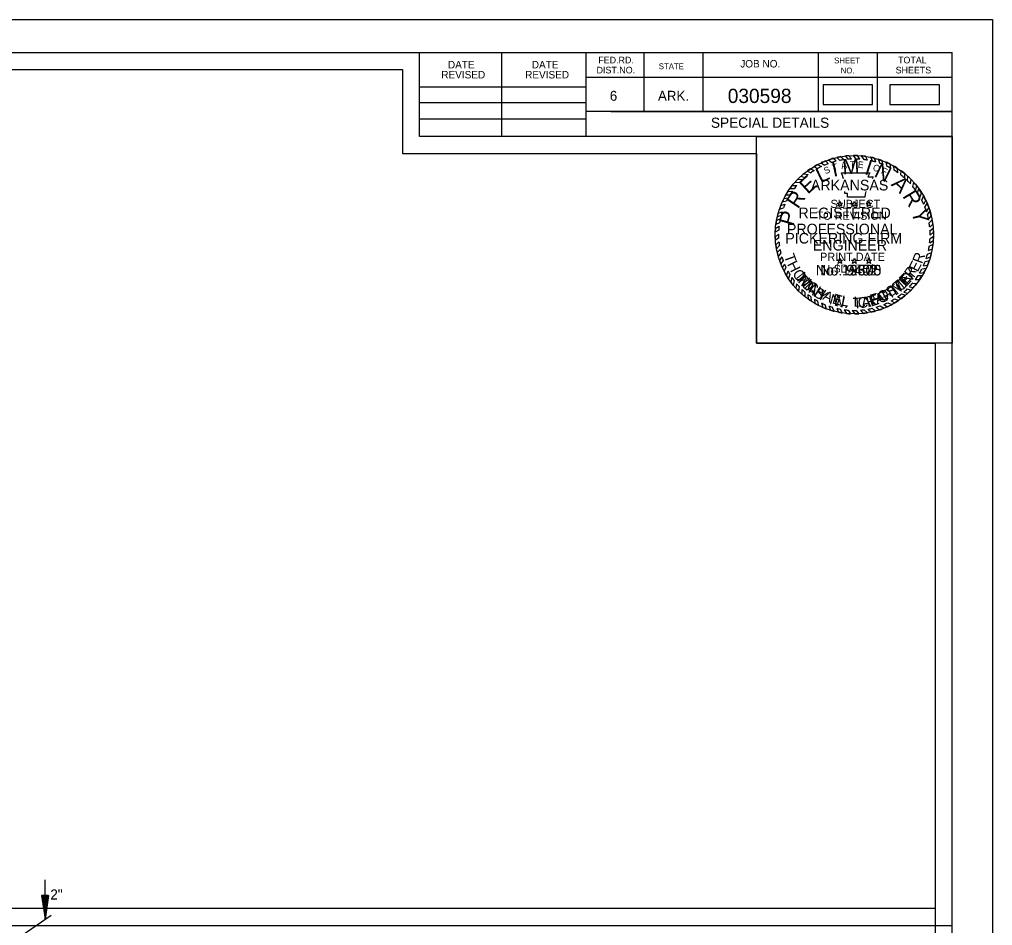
# Model space of a CAD drawing. Extents: x 1369904 to 1370238, y 380119 to 380332.
# Drawn here: x 1370123.3 to 1370237.7, y 380225.5 to 380332.1 of the extents above; entities that cross this region are included whole.
import ezdxf

# ---------------------------------------------------------------- set-up
doc = ezdxf.new("R2010")
doc.units = 0
for name, color, linetype in [('Default', 7, 'Continuous'), ('R_Border', 7, 'Continuous'), ('R_Border Notes', 7, 'Continuous'), ('R_Border Plan-Plan', 7, 'Continuous'), ('R_No Plot', 7, 'Continuous'), ('STAMP_PE_CRAFTON', 7, 'Continuous'), ('STAMP_PE_FOSTER', 7, 'Continuous'), ('STAMP_PE_SEAL-INFO', 7, 'Continuous'), ('STAMP_PE_TAEGTMEYER', 7, 'Continuous'), ('STAMP_PE_TXT', 7, 'Continuous'), ('STAMP_PRELIMINARY', 7, 'Continuous')]:
    doc.layers.add(name, color=color, linetype=linetype)

msp = doc.modelspace()

# ---------------------------------------------------------------- linework, layer by layer
at = {"layer": 'Default'}
for p, q in [((1370126.28, 380226.23), (1370126.28, 380230.86)), ((1370125.86, 380229.02), (1370126.28, 380226.23)), ((1370126.7, 380229.02), (1370125.86, 380229.02)), ((1370125.93, 380229.02), (1370126.28, 380226.69)), ((1370126.01, 380229.02), (1370126.28, 380227.17)), ((1370126.08, 380229.02), (1370126.28, 380227.64)), ((1370126.15, 380229.02), (1370126.28, 380228.11)), ((1370126.22, 380229.02), (1370126.28, 380228.57)), ((1370126.7, 380229.02), (1370126.28, 380226.23)), ((1370126.41, 380229.02), (1370126.28, 380228.11)), ((1370126.56, 380229.02), (1370126.28, 380227.17)), ((1370126.63, 380229.02), (1370126.28, 380226.69)), ((1370126.49, 380229.02), (1370126.28, 380227.64)), ((1370126.35, 380229.02), (1370126.28, 380228.57)), ((1370123.57, 380224.35), (1370126.98, 380226.71))]:
    msp.add_line(p, q, dxfattribs=at)
for points in [[(1370217.79, 380322.14), (1370223.62, 380322.14), (1370223.62, 380324.45), (1370217.79, 380324.45)], [(1370225.66, 380322.14), (1370231.49, 380322.14), (1370231.49, 380324.45), (1370225.66, 380324.45)]]:
    msp.add_lwpolyline(points, close=True, dxfattribs=at)
at = {"layer": 'R_Border'}
for p, q in [((1369916.79, 380328.24), (1370232.97, 380328.24)), ((1370170.33, 380318.36), (1370170.33, 380328.24)), ((1370180.01, 380318.36), (1370180.01, 380328.24)), ((1370189.87, 380328.24), (1370189.87, 380318.36)), ((1370196.71, 380328.24), (1370196.71, 380321.3)), ((1370203.65, 380328.24), (1370203.65, 380321.3)), ((1370217.23, 380328.24), (1370217.23, 380321.3)), ((1370224.17, 380328.24), (1370224.17, 380321.3)), ((1370232.97, 380122.78), (1370232.97, 380328.24)), ((1370232.97, 380325.3), (1370189.87, 380325.3)), ((1370232.97, 380325.32), (1370232.97, 380325.32)), ((1370170.33, 380324.22), (1370189.87, 380324.22)), ((1370170.33, 380322.36), (1370189.87, 380322.36)), ((1370232.97, 380321.3), (1370189.87, 380321.3)), ((1370192.83, 380321.3), (1370232.97, 380321.3)), ((1370170.33, 380320.42), (1370189.87, 380320.42)), ((1370232.97, 380318.36), (1370170.33, 380318.36))]:
    msp.add_line(p, q, dxfattribs=at)
at = {"layer": 'R_Border Plan-Plan'}
msp.add_line((1369916.79, 380225.51), (1370232.97, 380225.51), dxfattribs=at)
at = {"layer": 'R_No Plot'}
for points in [[(1369904.38, 380332.13), (1370237.72, 380332.13), (1370237.72, 380118.79), (1369904.38, 380118.79)], [(1370230.97, 380227.51), (1369918.79, 380227.51), (1369918.79, 380326.24), (1370168.33, 380326.24), (1370168.33, 380316.36), (1370185.87, 380316.36), (1370209.97, 380316.36), (1370209.97, 380294.02), (1370230.97, 380294.02)], [(1369918.79, 380326.24), (1370168.33, 380326.24), (1370168.33, 380316.36), (1370185.87, 380316.36), (1370209.97, 380316.36), (1370209.97, 380294.02), (1370230.97, 380294.02), (1370230.97, 380124.78), (1369918.79, 380124.78)], [(1370209.97, 380318.36), (1370232.97, 380318.36), (1370232.97, 380294.02), (1370209.97, 380294.02)]]:
    msp.add_lwpolyline(points, close=True, dxfattribs=at)
at = {"layer": 'STAMP_PE_SEAL-INFO'}
for p, q in [((1370217.58, 380315.27), (1370217.97, 380314.99)), ((1370218.08, 380315.49), (1370218.38, 380315.16)), ((1370218.43, 380315.61), (1370218.81, 380315.31)), ((1370219.02, 380315.8), (1370219.31, 380315.45)), ((1370219.41, 380315.89), (1370219.77, 380315.55)), ((1370219.89, 380315.99), (1370220.19, 380315.62)), ((1370220.41, 380316.06), (1370220.69, 380315.68)), ((1370221.14, 380315.71), (1370220.83, 380316.1)), ((1370221.64, 380315.71), (1370221.36, 380316.12)), ((1370222.1, 380315.69), (1370221.84, 380316.12)), ((1370222.61, 380315.64), (1370222.31, 380316.08)), ((1370223.03, 380315.58), (1370222.77, 380316.03)), ((1370223.59, 380315.46), (1370223.42, 380315.92)), ((1370223.99, 380315.35), (1370223.84, 380315.82)), ((1370224.45, 380315.2), (1370224.31, 380315.68)), ((1370224.86, 380315.04), (1370224.72, 380315.54)), ((1370225.33, 380314.84), (1370225.22, 380315.33)), ((1370215.89, 380314.3), (1370216.35, 380314.09)), ((1370216.31, 380314.56), (1370216.75, 380314.36)), ((1370216.7, 380314.81), (1370217.13, 380314.58)), ((1370217.14, 380315.06), (1370217.61, 380314.83)), ((1370219.94, 380314.09), (1370223.29, 380314.09)), ((1370220.07, 380313.78), (1370219.94, 380314.09)), ((1370223.29, 380314.09), (1370223.06, 380313.6)), ((1370225.77, 380314.61), (1370225.68, 380315.12)), ((1370226.16, 380314.38), (1370226.12, 380314.88)), ((1370226.59, 380314.09), (1370226.56, 380314.61)), ((1370226.95, 380313.83), (1370226.99, 380314.31)), ((1370214.51, 380313), (1370215.03, 380312.96)), ((1370214.83, 380313.35), (1370215.38, 380313.3)), ((1370215.17, 380313.67), (1370215.63, 380313.53)), ((1370215.51, 380313.97), (1370216.04, 380313.87)), ((1370220.17, 380313.49), (1370220.07, 380313.78)), ((1370220.18, 380313.37), (1370220.17, 380313.49)), ((1370223.06, 380313.6), (1370223.7, 380313.6)), ((1370223.7, 380313.6), (1370223.55, 380313.37)), ((1370227.4, 380313.46), (1370227.42, 380313.98)), ((1370227.71, 380313.16), (1370227.78, 380313.66)), ((1370228.07, 380312.79), (1370228.14, 380313.32)), ((1370228.35, 380312.47), (1370228.48, 380312.94)), ((1370213.65, 380311.88), (1370214.17, 380311.91)), ((1370213.89, 380312.22), (1370214.39, 380312.22)), ((1370214.17, 380312.59), (1370214.71, 380312.61)), ((1370220.37, 380311.66), (1370220.34, 380311.88)), ((1370222.81, 380311.88), (1370222.73, 380311.57)), ((1370228.67, 380312.06), (1370228.81, 380312.56)), ((1370228.89, 380311.74), (1370229.07, 380312.2)), ((1370212.99, 380310.66), (1370213.49, 380310.77)), ((1370213.18, 380311.05), (1370213.67, 380311.12)), ((1370213.41, 380311.48), (1370213.9, 380311.5)), ((1370220.68, 380311.66), (1370220.37, 380311.66)), ((1370220.68, 380311.23), (1370220.68, 380311.66)), ((1370222.71, 380311.23), (1370220.68, 380311.23)), ((1370222.73, 380311.57), (1370222.71, 380311.23)), ((1370229.2, 380311.24), (1370229.38, 380311.73)), ((1370229.4, 380310.88), (1370229.62, 380311.32)), ((1370229.63, 380310.39), (1370229.86, 380310.88)), ((1370212.5, 380309.32), (1370212.97, 380309.49)), ((1370212.65, 380309.82), (1370213.14, 380309.96)), ((1370212.8, 380310.23), (1370213.31, 380310.38)), ((1370229.77, 380310.06), (1370230.03, 380310.49)), ((1370229.96, 380309.51), (1370230.23, 380309.98)), ((1370230.07, 380309.14), (1370230.37, 380309.59)), ((1370212.76, 380308.67), (1370212.29, 380308.42)), ((1370212.39, 380308.91), (1370212.86, 380309.11)), ((1370230.21, 380308.58), (1370230.52, 380309.03)), ((1370230.27, 380308.2), (1370230.63, 380308.56)), ((1370212.58, 380307.35), (1370212.15, 380307.09)), ((1370212.61, 380307.77), (1370212.17, 380307.49)), ((1370212.67, 380308.21), (1370212.22, 380307.99)), ((1370230.34, 380307.69), (1370230.71, 380308.03)), ((1370230.37, 380307.28), (1370230.76, 380307.57)), ((1370212.56, 380306.86), (1370212.15, 380306.52)), ((1370212.57, 380306.45), (1370212.17, 380306.12)), ((1370230.33, 380305.85), (1370230.77, 380306.1)), ((1370230.37, 380306.35), (1370230.79, 380306.63)), ((1370230.39, 380306.76), (1370230.79, 380307.08)), ((1370212.6, 380305.95), (1370212.23, 380305.6)), ((1370212.65, 380305.52), (1370212.3, 380305.15)), ((1370212.73, 380305.06), (1370212.39, 380304.7)), ((1370230.19, 380304.96), (1370230.65, 380305.15)), ((1370230.28, 380305.46), (1370230.73, 380305.68)), ((1370212.82, 380304.65), (1370212.51, 380304.23)), ((1370212.95, 380304.2), (1370212.65, 380303.78)), ((1370213.09, 380303.78), (1370212.81, 380303.36)), ((1370229.8, 380303.63), (1370230.29, 380303.76)), ((1370229.94, 380304.01), (1370230.43, 380304.21)), ((1370230.09, 380304.51), (1370230.56, 380304.71)), ((1370213.25, 380303.35), (1370212.99, 380302.93)), ((1370213.43, 380302.97), (1370213.2, 380302.5)), ((1370229.43, 380302.78), (1370229.92, 380302.85)), ((1370229.59, 380303.12), (1370230.08, 380303.21)), ((1370213.66, 380302.51), (1370213.47, 380302.02)), ((1370213.9, 380302.1), (1370213.71, 380301.63)), ((1370214.1, 380301.79), (1370213.99, 380301.24)), ((1370228.64, 380301.51), (1370229.15, 380301.51)), ((1370228.98, 380302), (1370229.46, 380302)), ((1370229.16, 380302.28), (1370229.66, 380302.34)), ((1370214.38, 380301.4), (1370214.28, 380300.87)), ((1370214.68, 380301.02), (1370214.6, 380300.5)), ((1370214.99, 380300.69), (1370214.92, 380300.16)), ((1370215.31, 380300.36), (1370215.28, 380299.83)), ((1370227.7, 380300.42), (1370228.14, 380300.28)), ((1370227.95, 380300.68), (1370228.43, 380300.6)), ((1370228.34, 380301.11), (1370228.8, 380301.04)), ((1370215.65, 380300.05), (1370215.65, 380299.52)), ((1370216.01, 380299.75), (1370216.03, 380299.23)), ((1370216.35, 380299.5), (1370216.39, 380298.99)), ((1370216.78, 380299.22), (1370216.84, 380298.71)), ((1370226.22, 380299.26), (1370226.67, 380299.06)), ((1370226.56, 380299.48), (1370227, 380299.29)), ((1370227.02, 380299.83), (1370227.49, 380299.68)), ((1370227.29, 380300.05), (1370227.76, 380299.92)), ((1370217.13, 380299.02), (1370217.22, 380298.5)), ((1370217.61, 380298.77), (1370217.77, 380298.25)), ((1370217.98, 380298.6), (1370218.15, 380298.09)), ((1370218.47, 380298.41), (1370218.68, 380297.9)), ((1370218.88, 380298.27), (1370219.11, 380297.78)), ((1370219.39, 380298.13), (1370219.6, 380297.67)), ((1370219.79, 380298.05), (1370220.04, 380297.59)), ((1370223.56, 380298.14), (1370223.94, 380297.81)), ((1370224.02, 380298.26), (1370224.44, 380297.96)), ((1370224.52, 380298.42), (1370224.96, 380298.15)), ((1370224.94, 380298.59), (1370225.36, 380298.33)), ((1370225.4, 380298.8), (1370225.88, 380298.59)), ((1370225.8, 380299.01), (1370226.22, 380298.78)), ((1370220.29, 380297.97), (1370220.53, 380297.52)), ((1370220.73, 380297.92), (1370221, 380297.49)), ((1370221.21, 380297.89), (1370221.51, 380297.48)), ((1370221.67, 380297.89), (1370222.01, 380297.49)), ((1370222.19, 380297.92), (1370222.51, 380297.54)), ((1370222.63, 380297.96), (1370223, 380297.6)), ((1370223.07, 380298.03), (1370223.46, 380297.69))]:
    msp.add_line(p, q, dxfattribs=at)
for radius, start, end in [(9.32, 111.3124, 114.7026), (9.32, 105.2339, 109.0352), (8.91, 104.0352, 107.3615), (9.32, 99.7525, 102.7765), (8.91, 98.258, 101.0329), (9.32, 93.9381, 96.5517), (8.91, 92.1102, 95.0367), (9.32, 87.7298, 90.6707), (8.91, 85.9628, 88.9097), (9.32, 81.9732, 84.8236), (8.91, 79.9264, 82.696), (9.32, 75.3125, 77.9426), (8.91, 73.5575, 76.2314), (9.32, 69.6061, 72.3058), (8.91, 67.6248, 70.504), (9.32, 63.1329, 66.2704), (9.32, 123.6199, 126.5906), (8.91, 121.9746, 125.11), (9.32, 117.6544, 120.8099), (8.91, 115.6869, 119.1583), (8.91, 110.3086, 113.1659), (8.91, 61.1558, 64.3784), (9.32, 56.9003, 60.0942), (8.91, 54.9238, 58.2702), (9.32, 50.3492, 53.7159), (9.32, 135.4021, 138.3031), (8.91, 133.1331, 136.2562), (9.32, 129.7326, 132.5376), (8.91, 127.5297, 130.9683), (8.91, 48.3016, 52.0395), (8.91, 42.2212, 45.5512), (9.32, 44.3405, 47.3929), (9.32, 38.1247, 41.2316), (9.32, 147.0072, 149.899), (9.32, 141.6056, 144.4486), (8.91, 145.0197, 148.2104), (8.91, 139.301, 142.5873), (8.91, 36.135, 39.5311), (9.32, 31.9614, 35.4294), (9.32, 152.864, 155.5189), (8.91, 151.0315, 153.573), (8.91, 29.9032, 33.6645), (8.91, 23.7732, 27.2211), (9.32, 25.9391, 29.0125), (9.32, 158.4077, 161.0701), (8.91, 162.4331, 165.0013), (8.91, 156.3402, 159.2319), (8.91, 17.6802, 21.4251), (9.32, 19.9538, 23.3141), (9.32, 13.8421, 17.4447), (9.32, 170.0003, 172.6878), (9.32, 164.3068, 166.894), (8.91, 167.9048, 170.9039), (8.91, 11.5444, 15.2364), (9.32, 7.5852, 10.8621), (9.32, 175.7409, 178.2066), (8.91, 173.73, 176.4734), (8.91, 5.7599, 9.0606), (8.91, 359.7329, 3.0639), (9.32, 1.7215, 4.7268), (9.32, 181.7251, 184.1626), (8.91, 179.6454, 182.2633), (8.91, 353.8632, 357.1274), (9.32, 355.7156, 358.9569), (9.32, 187.4204, 190.1927), (8.91, 185.4539, 188.234), (8.91, 191.2274, 193.9858), (8.91, 348.0778, 351.3435), (9.32, 349.8305, 353.0885), (9.32, 193.0369, 195.9973), (9.32, 198.8967, 201.6281), (8.91, 196.9675, 199.8353), (8.91, 341.777, 345.0925), (9.32, 337.3837, 340.9933), (9.32, 343.8925, 347.035), (9.32, 204.5479, 207.4328), (8.91, 202.7761, 205.4791), (8.91, 329.5549, 333.2076), (8.91, 335.6038, 339.1858), (9.32, 331.4037, 334.9332), (9.32, 210.8636, 213.6571), (8.91, 208.7883, 211.7934), (8.91, 214.1838, 217.2747), (8.91, 323.5851, 327.4407), (9.32, 325.4405, 328.9872), (9.32, 216.6115, 219.491), (9.32, 222.48, 225.3801), (8.91, 220.3909, 223.3056), (8.91, 226.2494, 229.2407), (8.91, 310.7744, 314.3161), (8.91, 316.6531, 320.3711), (9.32, 318.2846, 321.8043), (9.32, 228.3665, 231.348), (8.91, 232.229, 234.9336), (9.32, 234.295, 236.9452), (8.91, 238.2223, 240.8353), (8.91, 299.0768, 302.1724), (8.91, 304.823, 308.5143), (9.32, 306.3721, 310.208), (9.32, 312.4518, 315.6633), (9.32, 240.1977, 242.8613), (8.91, 244.3204, 246.9486), (9.32, 246.576, 249.1558), (8.91, 250.3491, 253.1216), (8.91, 256.505, 259.1192), (8.91, 280.3459, 283.5814), (8.91, 286.6423, 289.9783), (9.32, 288.5709, 291.9733), (8.91, 292.8745, 296.1185), (9.32, 294.6481, 298.2166), (9.32, 300.621, 303.8703), (9.32, 252.5967, 255.3252), (9.32, 258.4433, 261.1398), (8.91, 262.3783, 265.2012), (9.32, 264.1978, 267.1009), (8.91, 268.3215, 271.277), (9.32, 270.2548, 273.3361), (8.91, 274.6157, 277.4486), (9.32, 276.4239, 279.4357), (9.32, 282.3199, 285.3702)]:
    msp.add_arc((1370221.47, 380306.8), radius, start, end, dxfattribs=at)
at = {"layer": 'STAMP_PE_TXT'}
for p, q in [((1370219.7, 380310.52), (1370219.77, 380310.75)), ((1370219.77, 380310.75), (1370219.85, 380310.52)), ((1370221.4, 380310.52), (1370221.47, 380310.75)), ((1370221.47, 380310.75), (1370221.55, 380310.52)), ((1370223.09, 380310.52), (1370223.17, 380310.75)), ((1370223.17, 380310.75), (1370223.25, 380310.52)), ((1370219.65, 380310.37), (1370219.45, 380310.52)), ((1370219.45, 380310.52), (1370219.7, 380310.52)), ((1370219.58, 380310.14), (1370219.65, 380310.37)), ((1370219.77, 380310.28), (1370219.58, 380310.14)), ((1370219.97, 380310.14), (1370219.77, 380310.28)), ((1370219.85, 380310.52), (1370220.09, 380310.52)), ((1370220.09, 380310.52), (1370219.9, 380310.37)), ((1370219.9, 380310.37), (1370219.97, 380310.14)), ((1370221.35, 380310.37), (1370221.15, 380310.52)), ((1370221.15, 380310.52), (1370221.4, 380310.52)), ((1370221.27, 380310.14), (1370221.35, 380310.37)), ((1370221.47, 380310.28), (1370221.27, 380310.14)), ((1370221.67, 380310.14), (1370221.47, 380310.28)), ((1370221.55, 380310.52), (1370221.79, 380310.52)), ((1370221.79, 380310.52), (1370221.59, 380310.37)), ((1370221.59, 380310.37), (1370221.67, 380310.14)), ((1370223.05, 380310.37), (1370222.85, 380310.52)), ((1370222.85, 380310.52), (1370223.09, 380310.52)), ((1370222.97, 380310.14), (1370223.05, 380310.37)), ((1370223.17, 380310.28), (1370222.97, 380310.14)), ((1370223.37, 380310.14), (1370223.17, 380310.28)), ((1370223.25, 380310.52), (1370223.49, 380310.52)), ((1370223.49, 380310.52), (1370223.29, 380310.37)), ((1370223.29, 380310.37), (1370223.37, 380310.14)), ((1370219.65, 380303.66), (1370219.45, 380303.81)), ((1370219.45, 380303.81), (1370219.7, 380303.81)), ((1370219.7, 380303.81), (1370219.77, 380304.04)), ((1370219.77, 380304.04), (1370219.85, 380303.81)), ((1370219.85, 380303.81), (1370220.09, 380303.81)), ((1370220.09, 380303.81), (1370219.9, 380303.66)), ((1370221.35, 380303.66), (1370221.15, 380303.81)), ((1370221.15, 380303.81), (1370221.4, 380303.81)), ((1370221.4, 380303.81), (1370221.47, 380304.04)), ((1370221.47, 380304.04), (1370221.55, 380303.81)), ((1370221.55, 380303.81), (1370221.79, 380303.81)), ((1370221.79, 380303.81), (1370221.59, 380303.66)), ((1370223.05, 380303.66), (1370222.85, 380303.81)), ((1370222.85, 380303.81), (1370223.09, 380303.81)), ((1370223.09, 380303.81), (1370223.17, 380304.04)), ((1370223.17, 380304.04), (1370223.25, 380303.81)), ((1370223.25, 380303.81), (1370223.49, 380303.81)), ((1370223.49, 380303.81), (1370223.29, 380303.66)), ((1370219.58, 380303.43), (1370219.65, 380303.66)), ((1370219.77, 380303.58), (1370219.58, 380303.43)), ((1370219.97, 380303.43), (1370219.77, 380303.58)), ((1370219.9, 380303.66), (1370219.97, 380303.43)), ((1370221.27, 380303.43), (1370221.35, 380303.66)), ((1370221.47, 380303.58), (1370221.27, 380303.43)), ((1370221.67, 380303.43), (1370221.47, 380303.58)), ((1370221.59, 380303.66), (1370221.67, 380303.43)), ((1370222.97, 380303.43), (1370223.05, 380303.66)), ((1370223.17, 380303.58), (1370222.97, 380303.43)), ((1370223.37, 380303.43), (1370223.17, 380303.58)), ((1370223.29, 380303.66), (1370223.37, 380303.43))]:
    msp.add_line(p, q, dxfattribs=at)
at = {"layer": 'STAMP_PRELIMINARY'}
msp.add_circle((1370221.47, 380306.8), 9.32, dxfattribs=at)

# ---------------------------------------------------------------- texts
at = {"layer": 'Default'}
msp.add_text('2"', height=1.181, dxfattribs=at).set_placement((1370126.9, 380228.56))
at = {"layer": 'R_Border'}
for s, height, p in [('DATE', 0.879, (1370173.67, 380326.37)), ('DATE', 0.879, (1370183.53, 380326.37)), ('FED.RD.', 0.782, (1370191.35, 380326.96)), ('STATE', 0.684, (1370198.47, 380326.28)), ('JOB NO.', 0.879, (1370208.05, 380326.48)), ('SHEET', 0.684, (1370219.09, 380326.96)), ('TOTAL', 0.782, (1370226.61, 380326.96)), ('REVISED', 0.879, (1370172.89, 380325.19)), ('REVISED', 0.879, (1370182.75, 380325.19)), ('DIST.NO.', 0.782, (1370191.15, 380325.78)), ('NO.', 0.684, (1370219.87, 380325.78)), ('SHEETS', 0.782, (1370226.33, 380325.78)), ('6', 1.17, (1370192.71, 380322.56)), ('ARK.', 1.172, (1370198.37, 380322.56))]:
    msp.add_text(s, height=height, dxfattribs=at).set_placement(p)
at = {"layer": 'R_Border Notes'}
for s, height, p in [('030598', 1.68, (1370206.58, 380322.3)), ('SPECIAL DETAILS', 1.2, (1370204.6, 380319.38))]:
    msp.add_text(s, height=height, dxfattribs=at).set_placement(p)
at = {"layer": 'STAMP_PE_CRAFTON'}
msp.add_text('No. 12370', height=1.25, dxfattribs=at).set_placement((1370216.93, 380302))
for s, rotation, p in [('T', 310.7442, (1370214.44, 380301.7)), ('O', 317.6422, (1370215.1, 380300.89)), ('O', 41.8391, (1370226.91, 380300.04)), ('N', 49.2411, (1370227.75, 380300.82)), ('N', 324.4537, (1370215.95, 380300.1)), ('Y', 331.1686, (1370216.98, 380299.39)), ('F', 28.7821, (1370225.13, 380298.93)), ('T', 34.1136, (1370226.05, 380299.44)), ('N', 347.4752, (1370219.04, 380298.47)), ('C', 6.0117, (1370221.94, 380298.14)), ('R', 14.8189, (1370223.04, 380298.26)), ('A', 20.5125, (1370224.15, 380298.56)), ('.', 356.8926, (1370220.27, 380298.19))]:
    msp.add_text(s, height=1.25, rotation=rotation, dxfattribs=at).set_placement(p)
at = {"layer": 'STAMP_PE_FOSTER'}
msp.add_text('No. 9402', height=1.25, dxfattribs=at).set_placement((1370217.46, 380302))
for s, rotation, p in [('R', 54.5031, (1370228.2, 380301.61)), ('M', 308.339, (1370214.59, 380301.82)), ('I', 314.1842, (1370215.39, 380300.88)), ('T', 39.4194, (1370226.61, 380300.04)), ('E', 46.9613, (1370227.47, 380300.79)), ('C', 319.8733, (1370215.74, 380300.53)), ('H', 327.7235, (1370216.67, 380299.79)), ('S', 31.7234, (1370225.66, 380299.41)), ('A', 335.7276, (1370217.65, 380299.21)), ('E', 343.5779, (1370218.79, 380298.74)), ('L', 350.8115, (1370219.85, 380298.47)), ('L', 1.2666, (1370221.39, 380298.31)), ('F', 15.8691, (1370223.51, 380298.55)), ('O', 23.719, (1370224.55, 380298.88)), ('.', 6.8035, (1370222.43, 380298.37))]:
    msp.add_text(s, height=1.2, rotation=rotation, dxfattribs=at).set_placement(p)
at = {"layer": 'STAMP_PE_TAEGTMEYER'}
for s, rotation, p in [('T', 289.646, (1370213.17, 380304.31)), ('H', 296.7339, (1370213.53, 380303.33)), ('E', 63.0984, (1370228.92, 380302.33)), ('R', 69.57, (1370229.42, 380303.31)), ('O', 303.7708, (1370214.12, 380302.22)), ('Y', 53.9986, (1370228.25, 380301.39)), ('M', 314.2033, (1370214.77, 380301.27)), ('E', 46.8094, (1370227.51, 380300.58)), ('A', 321.0594, (1370215.74, 380300.3)), ('S', 327.8239, (1370216.56, 380299.66)), ('T', 31.466, (1370225.57, 380299.15)), ('M', 39.3, (1370226.47, 380299.7)), ('N', 344.2727, (1370218.46, 380298.65)), ('T', 3.0061, (1370221.34, 380298.12)), ('A', 8.9826, (1370222.38, 380298.18)), ('E', 17.6836, (1370223.42, 380298.33)), ('G', 23.3052, (1370224.47, 380298.66)), ('.', 350.6464, (1370219.67, 380298.32))]:
    msp.add_text(s, height=1.25, rotation=rotation, dxfattribs=at).set_placement(p)
msp.add_text('No. 19605', height=1.25, dxfattribs=at).set_placement((1370216.93, 380302))
at = {"layer": 'STAMP_PE_TXT'}
for s, rotation, p in [('A', 9.0679, (1370219.96, 380314.53)), ('T', 1.8248, (1370220.94, 380314.66)), ('E', 355.2002, (1370221.85, 380314.67)), ('S', 23.5541, (1370218.07, 380313.9)), ('T', 16.311, (1370218.99, 380314.28)), ('O', 342.2506, (1370223.58, 380314.39)), ('F', 335.0075, (1370224.54, 380314.05))]:
    msp.add_text(s, height=0.781, rotation=rotation, dxfattribs=at).set_placement(p)
for s, p in [('ARKANSAS', (1370216.36, 380312.01)), ('REGISTERED', (1370214.89, 380308.74)), ('PROFESSIONAL', (1370213.54, 380306.84)), ('ENGINEER', (1370216.58, 380304.94))]:
    msp.add_text(s, height=1.25, dxfattribs=at).set_placement(p)
at = {"layer": 'STAMP_PRELIMINARY'}
for s, rotation, p in [('I', 12.5248, (1370219.01, 380313.59)), ('M', 3.1074, (1370220.11, 380313.9)), ('I', 342.3164, (1370222.58, 380313.96)), ('N', 333.9382, (1370223.68, 380313.69)), ('L', 25.513, (1370217.48, 380312.83)), ('E', 42.3578, (1370216, 380311.5)), ('A', 315.6579, (1370225.72, 380312.66)), ('R', 56.2292, (1370214.84, 380309.76)), ('R', 301.3831, (1370227.08, 380311.35)), ('P', 73.913, (1370214.29, 380307.74)), ('Y', 283.2593, (1370228.17, 380309.56))]:
    msp.add_text(s, height=1.8, rotation=rotation, dxfattribs=at).set_placement(p)
for s, height, p in [('SUBJECT', 0.96, (1370218.67, 380309.95)), ('TO REVISION', 0.96, (1370217.01, 380308.56)), ('PICKERING FIRM', 1.25, (1370213.35, 380305.76)), ('PRINT DATE', 0.96, (1370217.43, 380303.72)), ('$DATE$', 0.96, (1370219.11, 380302.33))]:
    msp.add_text(s, height=height, dxfattribs=at).set_placement(p)

doc.saveas('drawing.dxf')
